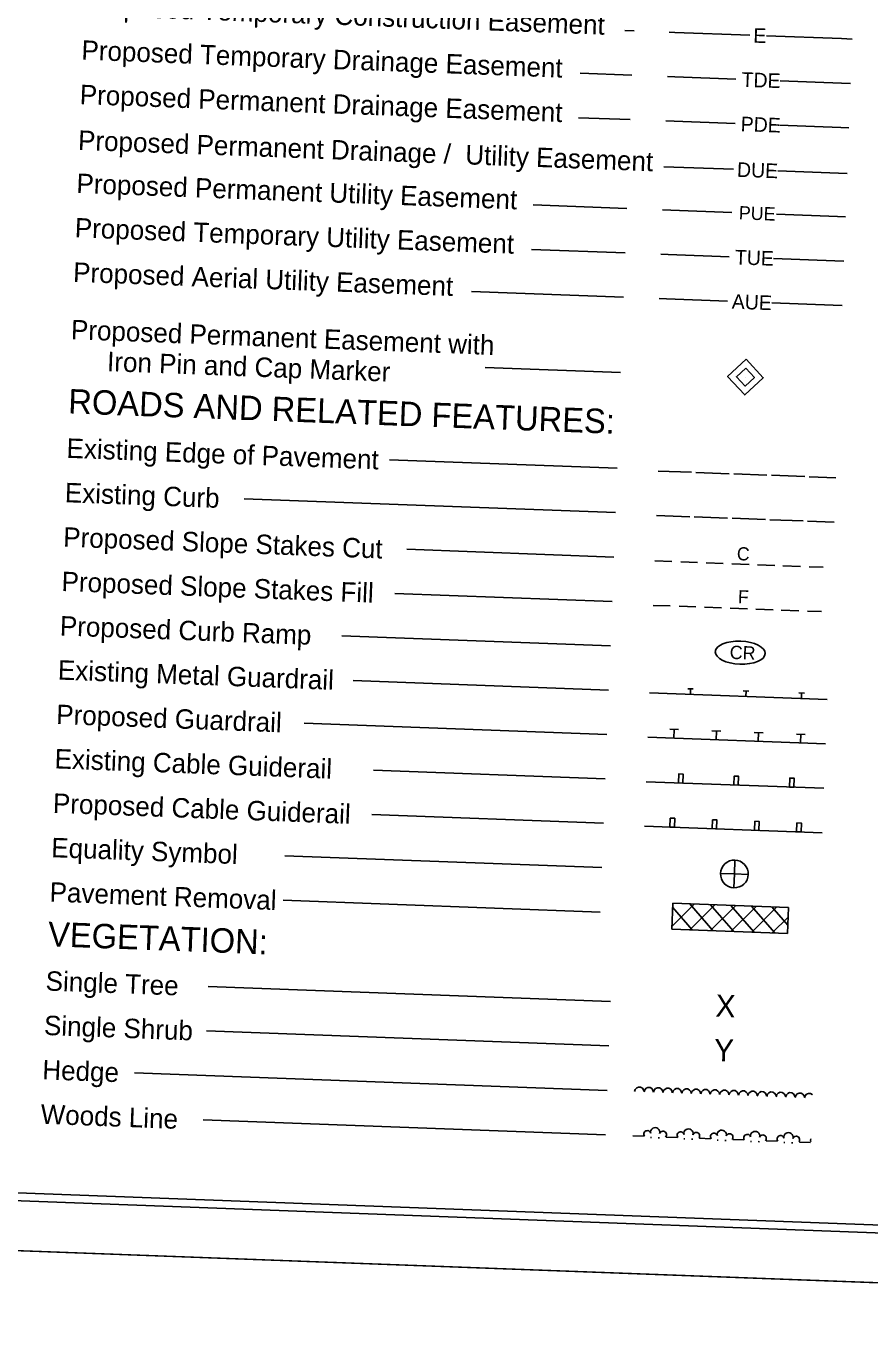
# Model space of a CAD drawing. Extents: x 2169602 to 2449496, y 721995 to 810662.
# Drawn here: x 2170556 to 2170935, y 721995 to 722588 of the extents above; entities that cross this region are included whole.
import ezdxf

# ---------------------------------------------------------------- set-up
doc = ezdxf.new("R2010")
doc.units = 0
for name, color, linetype in [('Prop Easement Permanent Drainage Utility', 7, 'Continuous'), ('Prop ROW Permanent Easement CELL', 7, 'Continuous'), ('Prop WCC CELL', 7, 'Continuous'), ('Sheet Cutting Line CELL', 7, 'Continuous'), ('Sheet Plot Border Inside CELL', 7, 'Continuous'), ('Sheet Plot Border Outside CELL', 7, 'Continuous'), ('Sheet Symbology CELL', 7, 'Continuous')]:
    doc.layers.add(name, color=color, linetype=linetype)

msp = doc.modelspace()

# ---------------------------------------------------------------- linework, layer by layer
at = {"layer": 'Prop Easement Permanent Drainage Utility'}
for p, q in [((2170842.76, 722525.06), (2170874.04, 722523.89)), ((2170894.03, 722523.14), (2170925.2, 722521.97))]:
    msp.add_line(p, q, dxfattribs=at)
at = {"layer": 'Prop ROW Permanent Easement CELL'}
msp.add_line((2170879.39, 722430.37), (2170879.39, 722430.37), dxfattribs=at)
for points in [[(2170879.69, 722438.42), (2170887.44, 722430.07), (2170879.09, 722422.33), (2170871.34, 722430.67)], [(2170879.54, 722434.4), (2170883.41, 722430.22), (2170879.24, 722426.35), (2170875.37, 722430.52)]]:
    msp.add_lwpolyline(points, close=True, dxfattribs=at)
at = {"layer": 'Prop WCC CELL'}
msp.add_ellipse((2170877.07, 722306.35), major_axis=(11.21, -0.42), ratio=0.462467, dxfattribs=at)
at = {"layer": 'Sheet Cutting Line CELL'}
msp.add_line((2169999.21, 722057.92), (2171682.03, 721994.96), dxfattribs=at)
at = {"layer": 'Sheet Plot Border Inside CELL'}
msp.add_lwpolyline([(2170013.04, 722079.86), (2171678.37, 722017.56), (2171717.82, 723071.92), (2170052.48, 723134.23)], close=True, dxfattribs=at)
at = {"layer": 'Sheet Plot Border Outside CELL'}
msp.add_lwpolyline([(2169999.21, 722057.92), (2171682.03, 721994.96), (2171723.16, 723094.19), (2170040.33, 723157.15)], close=True, dxfattribs=at)
at = {"layer": 'Sheet Symbology CELL'}
for p, q in [((2170829.39, 722586.18), (2170825.22, 722586.34)), ((2170845.03, 722585.6), (2170847.64, 722585.5)), ((2170847.64, 722585.5), (2170881.36, 722584.24)), ((2170888.86, 722583.96), (2170922.58, 722582.7)), ((2170922.58, 722582.7), (2170927.47, 722582.51)), ((2170828.26, 722566.21), (2170805.13, 722567.08)), ((2170844.28, 722565.61), (2170847.63, 722565.49)), ((2170847.63, 722565.49), (2170875.11, 722564.46)), ((2170895.09, 722563.71), (2170922.57, 722562.68)), ((2170922.57, 722562.68), (2170926.72, 722562.53)), ((2170827.51, 722546.22), (2170804.38, 722547.09)), ((2170843.53, 722545.63), (2170847.33, 722545.48)), ((2170847.33, 722545.48), (2170874.81, 722544.46)), ((2170894.79, 722543.71), (2170922.28, 722542.68)), ((2170922.28, 722542.68), (2170925.97, 722542.54)), ((2170826.02, 722506.24), (2170783.91, 722507.82)), ((2170842.03, 722505.64), (2170845.87, 722505.5)), ((2170845.87, 722505.5), (2170873.35, 722504.47)), ((2170893.34, 722503.73), (2170920.82, 722502.7)), ((2170920.82, 722502.7), (2170924.48, 722502.56)), ((2170825.27, 722486.26), (2170783.16, 722487.83)), ((2170841.29, 722485.66), (2170844.63, 722485.53)), ((2170844.63, 722485.53), (2170872.12, 722484.51)), ((2170892.1, 722483.76), (2170919.58, 722482.73)), ((2170919.58, 722482.73), (2170923.73, 722482.57)), ((2170824.52, 722466.27), (2170756.11, 722468.83)), ((2170840.54, 722465.67), (2170843.89, 722465.55)), ((2170843.89, 722465.55), (2170871.37, 722464.52)), ((2170891.35, 722463.77), (2170918.83, 722462.74)), ((2170918.83, 722462.74), (2170922.98, 722462.59)), ((2170823.26, 722432.47), (2170762.29, 722434.75)), ((2170821.64, 722389.35), (2170719.36, 722393.17)), ((2170840.14, 722388.08), (2170855.13, 722387.52)), ((2170857.13, 722387.44), (2170872.12, 722386.88)), ((2170874.11, 722386.81), (2170889.1, 722386.25)), ((2170891.1, 722386.17), (2170906.09, 722385.61)), ((2170908.09, 722385.54), (2170920.08, 722385.09)), ((2170820.89, 722369.36), (2170653.86, 722375.61)), ((2170839.39, 722368.09), (2170854.38, 722367.53)), ((2170856.38, 722367.46), (2170871.37, 722366.9)), ((2170873.37, 722366.82), (2170888.36, 722366.26)), ((2170890.35, 722366.19), (2170905.34, 722365.62)), ((2170907.34, 722365.55), (2170919.33, 722365.1)), ((2170820.15, 722349.37), (2170727.02, 722352.86)), ((2170838.62, 722347.63), (2170846.22, 722347.35)), ((2170857.91, 722346.91), (2170850.37, 722347.19)), ((2170869.4, 722346.48), (2170861.81, 722346.76)), ((2170881.15, 722346.04), (2170873.35, 722346.33)), ((2170892.59, 722345.61), (2170884.84, 722345.9)), ((2170904.13, 722345.18), (2170896.28, 722345.47)), ((2170914.42, 722344.8), (2170908.03, 722345.04)), ((2170819.4, 722329.39), (2170721.73, 722333.04)), ((2170837.88, 722327.65), (2170845.47, 722327.36)), ((2170857.16, 722326.92), (2170849.62, 722327.21)), ((2170868.66, 722326.49), (2170861.06, 722326.78)), ((2170880.4, 722326.05), (2170872.6, 722326.35)), ((2170891.84, 722325.63), (2170884.09, 722325.92)), ((2170903.38, 722325.2), (2170895.54, 722325.49)), ((2170913.67, 722324.81), (2170907.28, 722325.05)), ((2170818.65, 722309.4), (2170697.81, 722313.92)), ((2170817.75, 722289.54), (2170702.99, 722293.83)), ((2170836.25, 722288.27), (2170916.19, 722285.28)), ((2170853.47, 722290.13), (2170855.96, 722290.04)), ((2170854.62, 722287.59), (2170854.72, 722290.08)), ((2170878.45, 722289.2), (2170880.95, 722289.1)), ((2170879.6, 722286.65), (2170879.7, 722289.15)), ((2170903.43, 722288.26), (2170905.93, 722288.17)), ((2170904.59, 722285.72), (2170904.68, 722288.22)), ((2170817, 722269.56), (2170680.86, 722274.65)), ((2170915.44, 722265.3), (2170835.5, 722268.29)), ((2170845.37, 722271.87), (2170849.36, 722271.72)), ((2170847.22, 722267.85), (2170847.36, 722271.8)), ((2170864.35, 722271.16), (2170868.35, 722271.01)), ((2170866.2, 722267.14), (2170866.35, 722271.09)), ((2170883.34, 722270.45), (2170887.34, 722270.3)), ((2170885.19, 722266.43), (2170885.34, 722270.38)), ((2170902.33, 722269.74), (2170906.32, 722269.59)), ((2170904.18, 722265.72), (2170904.32, 722269.67)), ((2170816.26, 722249.57), (2170712.03, 722253.47)), ((2170834.75, 722248.3), (2170914.7, 722245.31)), ((2170815.51, 722229.58), (2170711.28, 722233.48)), ((2170834, 722228.32), (2170913.95, 722225.33)), ((2170814.76, 722209.6), (2170672.24, 722214.93)), ((2170874.69, 722213.02), (2170874.45, 722206.78)), ((2170868.21, 722207.01), (2170874.45, 722206.78)), ((2170874.45, 722206.78), (2170874.22, 722200.53)), ((2170874.45, 722206.78), (2170880.7, 722206.54)), ((2170814.01, 722189.61), (2170671.49, 722194.94)), ((2170846.23, 722181.99), (2170846.67, 722193.68)), ((2170846.27, 722183.14), (2170856.51, 722193.31)), ((2170855.47, 722181.64), (2170846.6, 722191.88)), ((2170846.65, 722193.08), (2170847.22, 722193.66)), ((2170846.67, 722193.68), (2170898.73, 722191.73)), ((2170864.77, 722181.3), (2170854.21, 722193.4)), ((2170854.38, 722181.68), (2170865.8, 722192.96)), ((2170874.01, 722180.95), (2170863.51, 722193.05)), ((2170863.62, 722181.34), (2170875.1, 722192.62)), ((2170883.3, 722180.6), (2170872.75, 722192.71)), ((2170872.91, 722180.99), (2170884.34, 722192.27)), ((2170892.6, 722180.25), (2170881.99, 722192.36)), ((2170882.21, 722180.64), (2170893.59, 722191.93)), ((2170898.43, 722183.79), (2170891.29, 722192.01)), ((2170898.73, 722191.73), (2170898.29, 722180.04)), ((2170891.45, 722180.3), (2170898.57, 722187.34)), ((2170898.29, 722180.04), (2170846.23, 722181.99)), ((2170818.65, 722149.34), (2170637.65, 722156.11)), ((2170817.9, 722129.35), (2170636.9, 722136.13)), ((2170817.15, 722109.37), (2170604.61, 722117.32)), ((2170829.54, 722108.91), (2170829.87, 722109.84)), ((2170829.87, 722109.84), (2170830.5, 722110.47)), ((2170830.5, 722110.47), (2170831.31, 722110.89)), ((2170831.31, 722110.89), (2170832.26, 722110.85)), ((2170832.26, 722110.85), (2170833.04, 722110.33)), ((2170833.04, 722110.33), (2170833.57, 722109.66)), ((2170833.57, 722109.66), (2170833.74, 722108.8)), ((2170833.78, 722108.75), (2170834.12, 722109.68)), ((2170834.12, 722109.68), (2170834.74, 722110.31)), ((2170834.74, 722110.31), (2170835.56, 722110.73)), ((2170835.56, 722110.73), (2170836.51, 722110.7)), ((2170836.51, 722110.7), (2170837.29, 722110.17)), ((2170837.29, 722110.17), (2170837.81, 722109.5)), ((2170837.81, 722109.5), (2170837.98, 722108.64)), ((2170838.03, 722108.59), (2170838.37, 722109.53)), ((2170838.37, 722109.53), (2170838.99, 722110.15)), ((2170838.99, 722110.15), (2170839.81, 722110.57)), ((2170839.81, 722110.57), (2170840.76, 722110.54)), ((2170840.76, 722110.54), (2170841.54, 722110.01)), ((2170841.54, 722110.01), (2170842.06, 722109.34)), ((2170842.06, 722109.34), (2170842.23, 722108.48)), ((2170842.28, 722108.43), (2170842.61, 722109.37)), ((2170842.61, 722109.37), (2170843.24, 722109.99)), ((2170843.24, 722109.99), (2170844.05, 722110.41)), ((2170844.05, 722110.41), (2170845, 722110.38)), ((2170845, 722110.38), (2170845.78, 722109.85)), ((2170845.78, 722109.85), (2170846.31, 722109.18)), ((2170846.31, 722109.18), (2170846.48, 722108.32)), ((2170846.52, 722108.27), (2170846.86, 722109.21)), ((2170846.86, 722109.21), (2170847.48, 722109.83)), ((2170847.48, 722109.83), (2170848.3, 722110.25)), ((2170848.3, 722110.25), (2170849.25, 722110.22)), ((2170849.25, 722110.22), (2170850.03, 722109.69)), ((2170850.03, 722109.69), (2170850.56, 722109.02)), ((2170850.56, 722109.02), (2170850.72, 722108.16)), ((2170850.77, 722108.11), (2170851.11, 722109.05)), ((2170851.11, 722109.05), (2170851.73, 722109.68)), ((2170851.73, 722109.68), (2170852.55, 722110.1)), ((2170852.55, 722110.1), (2170853.5, 722110.06)), ((2170853.5, 722110.06), (2170854.28, 722109.53)), ((2170854.28, 722109.53), (2170854.8, 722108.86)), ((2170854.8, 722108.86), (2170854.97, 722108)), ((2170855.02, 722107.95), (2170855.35, 722108.89)), ((2170855.35, 722108.89), (2170855.98, 722109.52)), ((2170855.98, 722109.52), (2170856.79, 722109.94)), ((2170856.79, 722109.94), (2170857.74, 722109.9)), ((2170857.74, 722109.9), (2170858.52, 722109.37)), ((2170858.52, 722109.37), (2170859.05, 722108.7)), ((2170859.05, 722108.7), (2170859.22, 722107.84)), ((2170859.27, 722107.79), (2170859.6, 722108.73)), ((2170859.6, 722108.73), (2170860.23, 722109.36)), ((2170860.23, 722109.36), (2170861.04, 722109.78)), ((2170861.04, 722109.78), (2170861.99, 722109.74)), ((2170861.99, 722109.74), (2170862.77, 722109.21)), ((2170862.77, 722109.21), (2170863.3, 722108.54)), ((2170863.3, 722108.54), (2170863.46, 722107.69)), ((2170863.51, 722107.63), (2170863.85, 722108.57)), ((2170863.85, 722108.57), (2170864.47, 722109.2)), ((2170864.47, 722109.2), (2170865.29, 722109.62)), ((2170865.29, 722109.62), (2170866.24, 722109.58)), ((2170866.24, 722109.58), (2170867.02, 722109.05)), ((2170867.02, 722109.05), (2170867.54, 722108.38)), ((2170867.54, 722108.38), (2170867.71, 722107.53)), ((2170867.76, 722107.48), (2170868.1, 722108.41)), ((2170868.1, 722108.41), (2170868.72, 722109.04)), ((2170868.72, 722109.04), (2170869.54, 722109.46)), ((2170869.54, 722109.46), (2170870.48, 722109.42)), ((2170870.48, 722109.42), (2170871.27, 722108.9)), ((2170871.27, 722108.9), (2170871.79, 722108.23)), ((2170871.79, 722108.23), (2170871.96, 722107.37)), ((2170872.01, 722107.32), (2170872.34, 722108.25)), ((2170872.34, 722108.25), (2170872.97, 722108.88)), ((2170872.97, 722108.88), (2170873.78, 722109.3)), ((2170873.78, 722109.3), (2170874.73, 722109.27)), ((2170874.73, 722109.27), (2170875.51, 722108.74)), ((2170875.51, 722108.74), (2170876.04, 722108.07)), ((2170876.04, 722108.07), (2170876.21, 722107.21)), ((2170876.25, 722107.16), (2170876.59, 722108.1)), ((2170876.59, 722108.1), (2170877.21, 722108.72)), ((2170877.21, 722108.72), (2170878.03, 722109.14)), ((2170878.03, 722109.14), (2170878.98, 722109.11)), ((2170878.98, 722109.11), (2170879.76, 722108.58)), ((2170879.76, 722108.58), (2170880.28, 722107.91)), ((2170880.28, 722107.91), (2170880.45, 722107.05)), ((2170880.5, 722107), (2170880.84, 722107.94)), ((2170880.84, 722107.94), (2170881.46, 722108.56)), ((2170881.46, 722108.56), (2170882.28, 722108.98)), ((2170882.28, 722108.98), (2170883.23, 722108.95)), ((2170883.23, 722108.95), (2170884.01, 722108.42)), ((2170884.01, 722108.42), (2170884.53, 722107.75)), ((2170884.53, 722107.75), (2170884.7, 722106.89)), ((2170884.75, 722106.84), (2170885.08, 722107.78)), ((2170885.08, 722107.78), (2170885.71, 722108.4)), ((2170885.71, 722108.4), (2170886.52, 722108.82)), ((2170886.52, 722108.82), (2170887.47, 722108.79)), ((2170887.47, 722108.79), (2170888.25, 722108.26)), ((2170888.25, 722108.26), (2170888.78, 722107.59)), ((2170888.78, 722107.59), (2170888.95, 722106.73)), ((2170889, 722106.68), (2170889.33, 722107.62)), ((2170889.33, 722107.62), (2170889.95, 722108.25)), ((2170889.95, 722108.25), (2170890.77, 722108.67)), ((2170890.77, 722108.67), (2170891.72, 722108.63)), ((2170891.72, 722108.63), (2170892.5, 722108.1)), ((2170892.5, 722108.1), (2170893.03, 722107.43)), ((2170893.03, 722107.43), (2170893.19, 722106.57)), ((2170893.24, 722106.52), (2170893.58, 722107.46)), ((2170893.58, 722107.46), (2170894.2, 722108.09)), ((2170894.2, 722108.09), (2170895.02, 722108.51)), ((2170895.02, 722108.51), (2170895.97, 722108.47)), ((2170895.97, 722108.47), (2170896.75, 722107.94)), ((2170896.75, 722107.94), (2170897.27, 722107.27)), ((2170897.27, 722107.27), (2170897.44, 722106.41)), ((2170897.49, 722106.36), (2170897.82, 722107.3)), ((2170897.82, 722107.3), (2170898.45, 722107.93)), ((2170898.45, 722107.93), (2170899.26, 722108.35)), ((2170899.26, 722108.35), (2170900.21, 722108.31)), ((2170900.21, 722108.31), (2170900.99, 722107.78)), ((2170900.99, 722107.78), (2170901.52, 722107.11)), ((2170901.52, 722107.11), (2170901.69, 722106.26)), ((2170901.74, 722106.2), (2170902.07, 722107.14)), ((2170902.07, 722107.14), (2170902.7, 722107.77)), ((2170902.7, 722107.77), (2170903.51, 722108.19)), ((2170903.51, 722108.19), (2170904.46, 722108.15)), ((2170904.46, 722108.15), (2170905.24, 722107.62)), ((2170905.24, 722107.62), (2170905.77, 722106.95)), ((2170905.98, 722106.05), (2170906.32, 722106.98)), ((2170906.32, 722106.98), (2170906.94, 722107.61)), ((2170906.94, 722107.61), (2170907.76, 722108.03)), ((2170907.76, 722108.03), (2170908.71, 722107.99)), ((2170908.71, 722107.99), (2170909.49, 722107.47)), ((2170909.49, 722107.47), (2170909.54, 722107.41)), ((2170905.77, 722106.95), (2170905.94, 722106.1)), ((2170816.41, 722089.38), (2170635.41, 722096.15)), ((2170828.79, 722088.92), (2170833.79, 722088.73)), ((2170836.71, 722088.12), (2170837.21, 722088.1)), ((2170840.21, 722087.99), (2170840.71, 722087.97)), ((2170843.78, 722088.36), (2170848.78, 722088.17)), ((2170851.7, 722087.56), (2170852.2, 722087.54)), ((2170855.2, 722087.43), (2170855.7, 722087.41)), ((2170858.77, 722087.8), (2170863.76, 722087.61)), ((2170866.69, 722087), (2170867.19, 722086.98)), ((2170870.19, 722086.87), (2170870.69, 722086.85)), ((2170873.76, 722087.24), (2170878.75, 722087.05)), ((2170881.68, 722086.44), (2170882.18, 722086.42)), ((2170885.18, 722086.31), (2170885.68, 722086.29)), ((2170888.75, 722086.68), (2170893.74, 722086.49)), ((2170896.67, 722085.88), (2170897.17, 722085.86)), ((2170900.17, 722085.75), (2170900.67, 722085.73)), ((2170903.74, 722086.12), (2170908.73, 722085.93))]:
    msp.add_line(p, q, dxfattribs=at)
for points in [[(2171705.23, 723069.84), (2170206.28, 723125.92), (2170167.06, 722077.67), (2171666.02, 722021.59)], [(2170849.22, 722247.76), (2170851.22, 722247.69), (2170851.37, 722251.68), (2170849.37, 722251.76)], [(2170874.2, 722246.83), (2170876.2, 722246.75), (2170876.35, 722250.75), (2170874.35, 722250.82)], [(2170899.18, 722245.89), (2170901.18, 722245.82), (2170901.33, 722249.81), (2170899.33, 722249.89)], [(2170845.61, 722231.88), (2170847.61, 722231.81), (2170847.46, 722227.81), (2170845.46, 722227.89)], [(2170864.6, 722231.17), (2170866.59, 722231.1), (2170866.44, 722227.1), (2170864.45, 722227.18)], [(2170883.58, 722230.46), (2170885.58, 722230.39), (2170885.43, 722226.39), (2170883.43, 722226.47)], [(2170902.57, 722229.75), (2170904.57, 722229.68), (2170904.42, 722225.68), (2170902.42, 722225.76)]]:
    msp.add_lwpolyline(points, close=True, dxfattribs=at)
for centre, radius, start, end in [((2170874.45, 722206.77), 6.25, 87.85179, 177.85633), ((2170874.45, 722206.77), 6.25, 357.85179, 87.85633), ((2170874.45, 722206.77), 6.25, 177.85179, 267.85633), ((2170874.45, 722206.77), 6.25, 267.85179, 357.85633), ((2170835.27, 722089.69), 1.58, 16.29236, 217.08892), ((2170838.81, 722090.56), 2.06, 343.82116, 191.89365), ((2170842.27, 722089.43), 1.58, 318.62589, 159.42246), ((2170850.26, 722089.13), 1.58, 16.29236, 217.08892), ((2170853.79, 722090), 2.06, 343.82116, 191.89365), ((2170857.25, 722088.87), 1.58, 318.62589, 159.42246), ((2170865.25, 722088.57), 1.58, 16.29236, 217.08892), ((2170868.78, 722089.44), 2.06, 343.82116, 191.89365), ((2170872.24, 722088.31), 1.58, 318.62589, 159.42246), ((2170880.24, 722088.01), 1.58, 16.29236, 217.08892), ((2170883.77, 722088.88), 2.06, 343.82116, 191.89365), ((2170887.23, 722087.75), 1.58, 318.62589, 159.42246), ((2170898.76, 722088.32), 2.06, 343.82116, 191.89365), ((2170895.23, 722087.45), 1.58, 16.29236, 217.08892), ((2170902.22, 722087.19), 1.58, 318.62589, 159.42246), ((2170910.22, 722086.89), 1.58, 154.10842, 201.60639)]:
    msp.add_arc(centre, radius, start, end, dxfattribs=at)

# ---------------------------------------------------------------- texts
at = {"layer": 'Prop Easement Permanent Drainage Utility'}
msp.add_text('DUE', height=6.55, rotation=357.85741, dxfattribs=at).set_placement((2170875.51, 722520.53))
at = {"layer": 'Prop WCC CELL'}
msp.add_text('CR', height=6, rotation=357.85741, dxfattribs=at).set_placement((2170872.25, 722303.57))
at = {"layer": 'Sheet Symbology CELL'}
for s, height, p in [('Proposed Temporary Construction Easement', 8.75, (2170581.35, 722593.2)), ('Proposed Temporary Drainage Easement', 8.75, (2170580.6, 722573.21)), ('E', 6.55, (2170882.84, 722580.88)), ('TDE', 6.55, (2170877.58, 722561.06)), ('Proposed Permanent Drainage Easement', 8.75, (2170579.85, 722553.23)), ('PDE', 6.55, (2170877.18, 722541.06)), ('Proposed Permanent Drainage /  Utility Easement', 8.75, (2170579.08, 722532.66)), ('Proposed Permanent Utility Easement', 8.75, (2170578.35, 722513.25)), ('PUE', 6, (2170876.34, 722501.36)), ('Proposed Temporary Utility Easement', 8.75, (2170577.61, 722493.26)), ('TUE', 6.55, (2170874.57, 722481.11)), ('Proposed Aerial Utility Easement', 8.75, (2170576.86, 722473.27)), ('AUE', 6.55, (2170873.17, 722461.15)), ('Proposed Permanent Easement with', 8.75, (2170575.89, 722447.43)), ('Iron Pin and Cap Marker', 8.75, (2170592.13, 722433.06)), ('ROADS AND RELATED FEATURES:', 11, (2170574.64, 722414.05)), ('Existing Edge of Pavement', 8.75, (2170573.9, 722394.06)), ('Existing Curb', 8.75, (2170573.15, 722374.08)), ('Proposed Slope Stakes Cut', 8.75, (2170572.4, 722354.09)), ('C', 5.93, (2170875.46, 722347.99)), ('Proposed Slope Stakes Fill', 8.75, (2170571.65, 722334.1)), ('F', 5.93, (2170875.94, 722328.59)), ('Proposed Curb Ramp', 8.75, (2170570.9, 722314.12)), ('Existing Metal Guardrail', 8.75, (2170570, 722294.26)), ('Proposed Guardrail', 8.75, (2170569.27, 722274.28)), ('Existing Cable Guiderail', 8.75, (2170568.52, 722254.3)), ('Proposed Cable Guiderail', 8.75, (2170567.77, 722234.31)), ('Equality Symbol', 8.75, (2170567.03, 722214.33)), ('Pavement Removal', 8.75, (2170566.28, 722194.34)), ('VEGETATION:', 11, (2170565.52, 722174.27)), ('Single Tree', 8.75, (2170564.49, 722154.32)), ('X', 10, (2170865.82, 722142.57)), ('Single Shrub', 8.75, (2170563.75, 722134.34)), ('Y', 10, (2170865.07, 722122.59)), ('Hedge', 8.75, (2170563, 722114.35)), ('Woods Line', 8.75, (2170562.25, 722094.36))]:
    msp.add_text(s, height=height, rotation=357.85741, dxfattribs=at).set_placement(p)

doc.saveas('drawing.dxf')
